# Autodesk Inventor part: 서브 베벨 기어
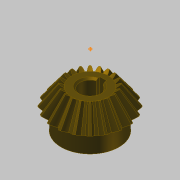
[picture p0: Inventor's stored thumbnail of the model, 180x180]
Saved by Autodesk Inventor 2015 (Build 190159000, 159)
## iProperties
Created: 2016-04
Part Number: 서브 베벨 기어
Material: 강철, 탄소
Document SubType Name: Modeling
Designer: mdu
Categories: <?xml version="1.0" encoding="UTF-16"?> <MemberInstance><Categories><FamilyTemplate><FamilyTemplateParameter ValueType="xs:double" Id="1" ObjectReferenceKey="da
Mass: 135.037 g
Surface Area: 63.6518 cm^2
Volume: 17.1585 cm^3
Density: 7.87 g/cm^3
Appearance: 얼룩무늬
CustomPartVersion: 1
Author: mdu
Revision Number: 1
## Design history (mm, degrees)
node "맨 위 점"
node "메쉬 평면2"
sketch "톱니 본체 스케치"
  geometry: L1 (0, 0)-(18.003, -31.331); L2 (18.003, -31.331)-(21.664, -28.891); L3 (21.664, -28.891)-(0, 0); L4 (20, -30)-(0, 0); L5 (10.813, -18.818)-(13.012, -17.352); L6 (18.003, -31.331)-(10.813, -18.818); L7 (21.664, -28.891)-(13.012, -17.352); L8 (0, -39.387)-(0, 6.564) reference; L9 (0, -30)-(21.664, -30)
  constraints: 16 end point, 4 point on line, 3 perpendicular, 2 collinear, 1 horizontal alignment, 1 vertical alignment
  dimensions: "d0" = 40 diameter of L4.start L8 (= da_de); "d1" = 36.00616 diameter of L1.end L8 (= da_dfe); "d2" = 43.3282 diameter of L2.end L8 (= da_dae); "d3" = 14.4 distance between parallel lines of L2 L5 (= da_b); "d4" = 28.8906 vertical distance of L2.end L1.start (= da_ve)
revolve "톱니 본체" sketch "톱니 본체 스케치" stored, may be unused: angle "d5" = 90 deg
node "시작점"
node "톱니 평면"
sketch "시작 스케치"
  geometry: L1 (0, -23.505)-(0, 10.645) reference; L2 (-0.834, -2.928)-(0.834, -2.928); A1 r 8.898 centre (-9.698, -3.713) between (-0.834, -2.928) and (-3.903, 3.04); A2 r 8.898 centre (9.698, -3.713) between (3.903, 3.04) and (0.834, -2.928); A3 r 27.357 centre (0, -24.037) between (3.903, 3.04) and (-3.903, 3.04); 1 further point
  constraints: 6 point on circle, 3 centre point, 3 symmetric about line, 2 end point, 1 coincident, 1 perpendicular, 1 other
  dimensions: "d7" = 8.89846 radius of A1 (= fd_rr); "d8" = 9.69794 horizontal distance of point (0, -24.037) A1.centre (= fd_x); "d9" = 20.32439 vertical distance of point (0, -24.037) A1.centre (= fd_y); "d57" = 27.35701 radius of A3 (= 0.5 x fd_dva + 0.3 x da_he); "d58" = 21.10901 distance from line of A3.centre L2 (= 0.5 x fd_dva - 1.12 x da_he)
node "끝점"
  node "끝 평면"
sketch "3D 스케치 오른쪽"
  node "Helical Curve Right" dims "d65" = 229.90621 (computed from da_dm, da_delta, da_beta), "d66" = 31.5, "d67" = 40 (= da_de), "d68" = -5.88003 (= -da_delta), "d69" = 12.16458 (computed from fd_loft, da_delta)
node "끝 평면 오른쪽"
sketch "끝 스케치 오른쪽"
  geometry: L1 (0, -22.649)-(0, 12.15) reference; L2 (-0.497, -1.72)-(0.497, -1.72); A1 r 5.299 centre (-5.775, -2.187) between (-0.497, -1.72) and (-2.324, 1.834); A2 r 5.299 centre (5.775, -2.187) between (2.324, 1.834) and (0.497, -1.72); A3 r 16.291 centre (0, -14.29) between (2.324, 1.834) and (-2.324, 1.834); 1 further point
  constraints: 6 point on circle, 3 centre point, 3 symmetric about line, 2 end point, 1 coincident, 1 perpendicular, 1 other
  dimensions: "d70" = 5.77526 horizontal distance of A3.centre A1.centre (computed from fd_x, fd_ratio); "d71" = 12.10346 vertical distance of point (0, -14.29) A1.centre (computed from fd_y, fd_ratio); "d72" = 5.29916 radius of A1 (computed from fd_rr, fd_ratio); "d73" = 12.57071 distance from line of point (0, -14.29) L2 (computed from d58, fd_ratio); "d74" = 16.29149 radius of A3 (computed from d57, fd_ratio)
feature "로프트 오른쪽" sketch "끝 스케치 오른쪽" dims "d75" = 0, "d77" = 0, "d79" = 0, "d80" = 90 deg, "d85" = 20, "d92" = 90 deg, "d93" = 90 deg, "da_teethtype" = 0 [user parameter]
sketch "3D 스케치 왼쪽"
  node "Helical Curve Left" dims "d26" = 229.90621 (computed from da_dm, da_delta, da_beta), "d27" = 12.16458 (computed from fd_loft, da_delta), "d28" = 40 (= da_de), "d29" = -5.88003 (= -da_delta)
node "끝 평면 왼쪽"
sketch "끝 스케치 왼쪽" dims "d56" = 10.82768 (derived)
  geometry: L1 (0, -35.087)-(0, 18.089) reference; L2 (-0.497, -1.716)-(0.497, -1.716); A1 r 5.299 centre (-5.775, -2.183) between (-0.497, -1.716) and (-2.324, 1.838); A2 r 5.299 centre (5.775, -2.183) between (2.324, 1.838) and (0.497, -1.716); A3 r 16.291 centre (0, -14.287) between (2.324, 1.838) and (-2.324, 1.838); 2 further points; 1 other entity
  constraints: 6 point on circle, 3 centre point, 3 symmetric about line, 2 end point, 1 coincident, 2 other
  dimensions: "d30" = 5.29916 radius of A1 (computed from fd_rr, fd_ratio); "d31" = 5.77526 horizontal distance of point (0, -14.287) A1.centre (computed from fd_x, fd_ratio); "d32" = 12.10346 vertical distance of A1.centre point (0, -14.287) (computed from fd_y, fd_ratio); "d61" = 16.29149 radius of A3 (computed from d57, fd_ratio); "d62" = 12.57071 distance from line of point (0, -14.287) L2 (computed from d58, fd_ratio)
feature "로프트 왼쪽" sketch "끝 스케치 왼쪽" dims "d35" = 0, "d37" = 0, "d39" = 0, "d40" = 90 deg, "d84" = 10, "d90" = 90 deg, "d91" = 90 deg, "da_teethtype" = 0 [user parameter]
sketch "본체 스케치"
  geometry: L1 (0, -35.038)-(0, -19.531) reference; L2 (18.003, -31.331)-(10.813, -18.818) reference; L3 (10.813, -18.818)-(0, -18.818); L4 (18.003, -31.331)-(0, -31.331)
  constraints: 4 end point, 2 perpendicular, 2 point on line
revolve "본체 고정" sketch "본체 스케치" stored, may be unused: angle "d46" = 90 deg
feature "피치 지름" dims angle "d47" = 90 deg
sketch "스케치8"
  geometry: C1 r 17 at (0, 0); 1 further point
  constraints: 1 centre point, 1 coincident
  dimensions: "d94" = 34 diameter of C1
extrude "돌출1" join sketch "스케치8" distance "d95" = 10; taper "d96" = 0 deg
sketch "스케치9"
  geometry: 1 further point
hole "구멍1" sketch "스케치9" at (0, 0) diameter "d97" = 12; stored, may be unused: countersink angle "d101" = 90 deg, drill point angle "d103" = 118 deg; dims "d98" = 6, "d99" = 4, "d100" = 2, "d102" = 8
sketch "스케치10"
  geometry: 1 further point
sketch "스케치11"
  geometry: 1 further point
sketch "스케치12"
  geometry: L1 (-2, 5.657)-(-2, 7.8); L2 (-2, 7.8)-(2, 7.8); L3 (2, 7.8)-(2, 5.657); A1 r 6 centre (0, 0) between (-2, 5.657) and (2, 5.657) reference; 1 further point
  constraints: 6 end point, 2 parallel, 2 point on circle, 1 perpendicular, 1 vertical
  dimensions: "d104" = 4 distance of L1.end L2.end; "d105" = 13.8 dimension on A1 L2
extrude "돌출2" cut sketch "스케치12" stored distance "d106" = 7; taper "d107" = 0 deg
chamfer "모따기1" distance "d108" = 1; stored, may be unused: second distance "d109" = 2, angle "d110" = 45 deg
body "Solid1"
feature "로프트" dims "d17" = 0, "d18" = 90 deg, "d19" = 0, "d20" = 90 deg, "d89" = 0, "da_teethtype" = 0 [user parameter]
pattern_circular "원형 패턴" dims angle "d22" = 360 deg, "d88" = 0, "da_teethtype" = 0 [user parameter]
pattern_circular "원형 패턴 오른쪽" dims angle "d82" = 360 deg, "da_teethtype" = 0 [user parameter]
pattern_circular "원형 패턴 왼쪽" dims angle "d42" = 360 deg, "da_teethtype" = 0 [user parameter]
sketch "끝 스케치"
  geometry: L1 (0, -15.359)-(0, 6.983) reference; L2 (-0.497, -1.72)-(0.497, -1.72); A1 r 5.299 centre (-5.775, -2.187) between (-0.497, -1.72) and (-2.324, 1.834); A2 r 5.299 centre (5.775, -2.187) between (2.324, 1.834) and (0.497, -1.72); A3 r 16.291 centre (0, -14.29) between (2.324, 1.834) and (-2.324, 1.834); 1 further point
  constraints: 6 point on circle, 3 centre point, 3 symmetric about line, 2 end point, 1 coincident, 1 other
  dimensions: "d12" = 5.29916 radius of A1 (computed from fd_rr, fd_ratio); "d15" = 5.77526 horizontal distance of A1.centre point (0, -14.29) (computed from fd_x, fd_ratio); "d16" = 12.10346 vertical distance of A1.centre point (0, -14.29) (computed from fd_y, fd_ratio); "d59" = 16.29149 radius of A3 (computed from d57, fd_ratio); "d60" = 12.57071 distance from line of A3.centre L2 (computed from d58, fd_ratio)
sketch "Sketch6"
  geometry: L1 (20, -30)-(0, 0) reference; L2 (0, -37.8)-(0, 6.3) reference
body "Srf1"
other parameters: "da_b" = 14.4 [user parameter; used in 2 equation terms], "da_de" = 40 [user parameter; used in 4 equation terms], "da_dae" = 43.3282 [user parameter; used in 2 equation terms], "da_dfe" = 36.00616 [user parameter; used in 1 equation term], "da_le" = 36.05551 [user parameter; used in 1 equation term], "da_omega" = 90 deg [user parameter; used in 1 equation term], "da_beta" = 0 [user parameter; used in 2 equation terms], "da_delta" = 5.88003 [user parameter; used in 8 equation terms], "da_alpha" = 20 deg [user parameter; used in 2 equation terms], "da_he" = 4.4 [user parameter; used in 4 equation terms], "da_ve" = 28.8906 [user parameter; used in 1 equation term], "fd_dv" = 48.07402 (computed from da_de, da_delta) [user parameter; used in 1 equation term], "fd_dva" = 52.07402 (computed from da_dae, da_delta) [user parameter; used in 3 equation terms], "fd_dvb" = 45.1748 (computed from fd_dv, da_alpha) [user parameter; used in 2 equation terms], "da_zv" = 240.37008 [user parameter; used in 1 equation term], "fd_loft" = 14.62 (= da_b + 0.05 x da_he) [user parameter; used in 4 equation terms], "fd_ratio" = 5.95514 (computed from da_le, fd_loft) [user parameter; used in 15 equation terms], "fd_rr" = 8.89846 (computed from fd_dd, fd_dvb) [user parameter; used in 6 equation terms], "fd_angle" = 0.66075 (computed from da_zv) [user parameter; used in 4 equation terms], "fd_x1" = 1.58709 (computed from da_dvw, fd_angle) [user parameter; used in 1 equation term], "fd_y1" = 23.98456 (computed from da_dvw, fd_angle) [user parameter; used in 1 equation term], "fd_x2" = 8.11084 (computed from fd_rr, fd_angle2, fd_angle) [user parameter; used in 1 equation term], "fd_y2" = 3.66016 (computed from fd_rr, fd_angle2, fd_angle) [user parameter; used in 1 equation term], "fd_x" = 9.69794 (= fd_x1 + fd_x2) [user parameter; used in 4 equation terms], "fd_y" = 20.32439 (= fd_y1 - fd_y2) [user parameter; used in 4 equation terms], "fd_angle2" = 3.57832 (computed from fd_dvb, fd_dd, da_alpha) [user parameter; used in 2 equation terms], "fd_dd" = 48.55402 (= fd_dva - 0.8 x da_he) [user parameter; used in 2 equation terms], "da_dvw" = 48.07402 [user parameter; used in 2 equation terms], "d11" = 14.62 (= fd_loft), "da_dm" = 32.01232 [user parameter; used in 2 equation terms], "da_x" = 0 [user parameter], "da_m" = 2 [user parameter], "d48" = 0, "d49" = 0, "d50" = 90 deg (= da_omega), "d51" = 9 deg (computed from da_z), "d52" = 0, "d53" = 0, "d54" = 0
